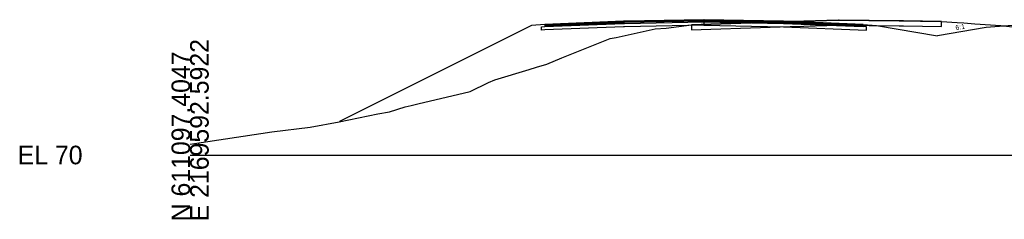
# Model space of a CAD drawing. Extents: x -26 to 1303, y -3010 to 12033.
# Drawn here: x 974.3 to 1122.8, y 6490.3 to 6520.4 of the extents above; entities that cross this region are included whole.
import ezdxf

# ---------------------------------------------------------------- set-up
doc = ezdxf.new("R2010")
doc.units = 0
for name, color, linetype in [('RD_GPK_XS_Cell', 7, 'Continuous'), ('RD_XS_Base', 7, 'Continuous'), ('RD_XS_ExGround', 7, 'Continuous'), ('RD_XS_ExPaveRet', 7, 'Continuous'), ('RD_XS_Greenside', 7, 'Continuous'), ('RD_XS_Pave', 7, 'Continuous'), ('RD_XS_PaveOvlay_CP', 7, 'Continuous'), ('RD_XS_TieSlope', 7, 'Continuous'), ('RD_XS_TX_Slope', 7, 'Continuous')]:
    doc.layers.add(name, color=color, linetype=linetype)

msp = doc.modelspace()

# ---------------------------------------------------------------- linework, layer by layer
at = {"layer": 'RD_GPK_XS_Cell'}
msp.add_line((1000, 6500), (1150, 6500), dxfattribs=at)
at = {"layer": 'RD_XS_Base'}
for p, q in [((1053.47, 6519.36), (1065.35, 6519.83)), ((1065.35, 6519.83), (1065.47, 6519.84)), ((1065.47, 6519.84), (1077.46, 6520.08)), ((1077.46, 6520.08), (1077.47, 6520.08)), ((1077.47, 6520.08), (1077.47, 6520.24)), ((1077.47, 6520.24), (1077.47, 6520.24)), ((1077.47, 6520.24), (1077.47, 6520.24)), ((1077.47, 6520.24), (1077.47, 6519.58)), ((1077.47, 6520.08), (1077.47, 6520.24)), ((1077.47, 6520.24), (1077.47, 6519.58)), ((1077.47, 6520.08), (1077.47, 6520.08)), ((1077.47, 6520.08), (1077.47, 6519.58)), ((1077.49, 6520.08), (1077.47, 6520.08)), ((1077.47, 6520.08), (1077.47, 6519.58)), ((1089.47, 6519.84), (1077.47, 6520.08)), ((1077.47, 6520.08), (1077.47, 6520.08)), ((1101.47, 6519.36), (1089.47, 6519.84)), ((1091.47, 6519.76), (1091.47, 6519.76)), ((1052.97, 6519.34), (1053.46, 6519.36)), ((1052.97, 6519.33), (1052.97, 6519.34)), ((1052.97, 6518.84), (1052.97, 6519.33)), ((1053.46, 6518.86), (1052.97, 6518.84)), ((1053.46, 6519.36), (1053.47, 6519.36)), ((1053.47, 6518.86), (1053.46, 6518.86)), ((1065.35, 6519.33), (1053.47, 6518.86)), ((1065.47, 6519.34), (1065.35, 6519.33)), ((1077.46, 6519.58), (1065.47, 6519.34)), ((1077.47, 6519.58), (1077.46, 6519.58)), ((1077.47, 6519.58), (1077.49, 6519.58)), ((1077.47, 6519.58), (1077.47, 6519.58)), ((1077.47, 6519.58), (1077.47, 6519.58)), ((1077.47, 6519.58), (1089.47, 6519.34)), ((1089.47, 6519.34), (1101.97, 6518.84)), ((1091.47, 6519.26), (1091.47, 6519.26)), ((1101.97, 6519.34), (1101.47, 6519.36)), ((1101.47, 6519.36), (1101.47, 6519.36)), ((1101.97, 6518.84), (1101.97, 6519.34)), ((1101.97, 6519.34), (1101.97, 6519.34)), ((1101.97, 6518.84), (1101.97, 6518.84)), ((1101.97, 6518.84), (1101.97, 6518.84))]:
    msp.add_line(p, q, dxfattribs=at)
at = {"layer": 'RD_XS_ExGround'}
msp.add_lwpolyline([(1000, 6501.64), (1012.31, 6503.47), (1018.1, 6504.19), (1022.48, 6505.02), (1028.31, 6506.21), (1030.05, 6506.49), (1032.43, 6507.28), (1033.34, 6507.48), (1034.34, 6507.73), (1042.21, 6509.55), (1044.98, 6510.92), (1045.94, 6511.35), (1051.14, 6512.9), (1052.23, 6513.25), (1053.8, 6513.7), (1056.05, 6514.64), (1063.34, 6517.57), (1064.25, 6517.73), (1070.09, 6519), (1071.78, 6519.12), (1075.61, 6519.63), (1090.46, 6520.11), (1097.77, 6520.34), (1106.9, 6520.22), (1113.29, 6520.13), (1115.64, 6519.97), (1116.64, 6519.9), (1118.29, 6519.78), (1122.24, 6519.5), (1130.02, 6518.62)], dxfattribs=at)
at = {"layer": 'RD_XS_ExPaveRet'}
for points in [[(1075.61, 6519.63), (1075.61, 6519.63), (1075.61, 6519.63), (1075.61, 6518.96), (1075.61, 6518.88), (1075.61, 6518.88), (1075.61, 6518.88), (1078.52, 6518.97), (1090.46, 6519.36), (1090.79, 6519.37), (1097.77, 6519.59), (1097.83, 6519.59), (1106.9, 6519.47), (1107.54, 6519.46), (1113.29, 6519.38), (1113.29, 6519.38), (1113.29, 6519.38), (1113.29, 6520.09), (1113.29, 6520.13), (1113.29, 6520.13), (1113.29, 6520.13), (1107.54, 6520.21), (1106.9, 6520.22), (1097.83, 6520.34), (1097.77, 6520.34), (1090.79, 6520.12), (1090.46, 6520.11), (1078.52, 6519.72), (1075.61, 6519.63)], [(1075.61, 6519.63), (1075.61, 6519.63), (1075.61, 6518.96), (1075.61, 6518.88), (1075.61, 6518.88), (1078.52, 6518.97), (1090.46, 6519.36), (1090.79, 6519.37), (1097.77, 6519.59), (1097.83, 6519.59), (1106.9, 6519.47), (1107.54, 6519.46), (1113.29, 6519.38), (1113.29, 6519.38), (1113.29, 6520.09), (1113.29, 6520.13), (1113.29, 6520.13), (1107.54, 6520.21), (1106.9, 6520.22), (1097.83, 6520.34), (1097.77, 6520.34), (1090.79, 6520.12), (1090.46, 6520.11), (1078.52, 6519.72), (1075.61, 6519.63)]]:
    msp.add_lwpolyline(points, dxfattribs=at)
at = {"layer": 'RD_XS_Greenside'}
for p, q in [((1051.47, 6519.52), (1022.54, 6505.06)), ((1103.47, 6519.52), (1112.69, 6517.98)), ((1120, 6519.2), (1112.69, 6517.98))]:
    msp.add_line(p, q, dxfattribs=at)
at = {"layer": 'RD_XS_Pave'}
for p, q in [((1065.35, 6520.15), (1053.47, 6519.68)), ((1065.35, 6519.99), (1053.47, 6519.52)), ((1053.47, 6519.52), (1065.35, 6519.99)), ((1053.47, 6519.36), (1065.35, 6519.83)), ((1053.47, 6519.68), (1053.47, 6519.67)), ((1053.47, 6519.67), (1053.47, 6519.52)), ((1065.47, 6520.16), (1065.35, 6520.15)), ((1065.47, 6520), (1065.35, 6519.99)), ((1065.35, 6519.99), (1065.47, 6520)), ((1065.35, 6519.83), (1065.47, 6519.84)), ((1077.46, 6520.4), (1065.47, 6520.16)), ((1077.46, 6520.24), (1065.47, 6520)), ((1065.47, 6520), (1077.46, 6520.24)), ((1065.47, 6519.84), (1077.46, 6520.08)), ((1077.47, 6520.4), (1077.46, 6520.4)), ((1077.47, 6520.24), (1077.46, 6520.24)), ((1077.46, 6520.24), (1077.47, 6520.24)), ((1077.46, 6520.08), (1077.47, 6520.08)), ((1077.49, 6520.4), (1077.47, 6520.4)), ((1089.47, 6520.16), (1077.47, 6520.4)), ((1077.47, 6520.08), (1077.47, 6520.24)), ((1077.47, 6520.24), (1077.47, 6520.24)), ((1077.47, 6520.24), (1077.49, 6520.24)), ((1077.49, 6520.24), (1077.47, 6520.24)), ((1077.47, 6520.24), (1077.47, 6520.24)), ((1077.47, 6520.24), (1077.47, 6520.08)), ((1077.47, 6520.08), (1077.47, 6520.24)), ((1077.47, 6520.24), (1089.47, 6520)), ((1089.47, 6520), (1077.47, 6520.24)), ((1077.47, 6520.24), (1077.47, 6520.08)), ((1077.47, 6520.08), (1077.49, 6520.08)), ((1077.47, 6520.08), (1077.47, 6520.08)), ((1077.47, 6520.08), (1077.47, 6520.08)), ((1077.47, 6520.08), (1089.47, 6519.84)), ((1101.47, 6519.68), (1089.47, 6520.16)), ((1089.47, 6520), (1101.47, 6519.52)), ((1101.47, 6519.52), (1089.47, 6520)), ((1089.47, 6519.84), (1101.47, 6519.36)), ((1091.47, 6520.08), (1091.47, 6520.08)), ((1091.47, 6519.92), (1091.47, 6519.92)), ((1091.47, 6519.92), (1091.47, 6519.92)), ((1091.47, 6519.76), (1091.47, 6519.76)), ((1101.47, 6519.52), (1101.47, 6519.68)), ((1101.47, 6519.68), (1101.47, 6519.68)), ((1053.47, 6519.52), (1053.47, 6519.52)), ((1053.47, 6519.52), (1053.47, 6519.36)), ((1101.47, 6519.52), (1101.47, 6519.52)), ((1101.47, 6519.52), (1101.47, 6519.52)), ((1101.47, 6519.36), (1101.47, 6519.52)), ((1101.47, 6519.52), (1101.47, 6519.52)), ((1101.47, 6519.36), (1101.47, 6519.36)), ((1101.47, 6519.36), (1101.47, 6519.36))]:
    msp.add_line(p, q, dxfattribs=at)
at = {"layer": 'RD_XS_PaveOvlay_CP'}
for p, q in [((1053.47, 6519.68), (1065.47, 6520.16)), ((1065.47, 6520.16), (1077.47, 6520.4)), ((1077.47, 6520.4), (1089.47, 6520.16)), ((1089.47, 6520.16), (1101.47, 6519.68))]:
    msp.add_line(p, q, dxfattribs=at)
at = {"layer": 'RD_XS_TieSlope'}
for p, q in [((1053.47, 6519.68), (1051.47, 6519.52)), ((1101.47, 6519.68), (1103.47, 6519.52)), ((1126, 6519.68), (1120, 6519.2))]:
    msp.add_line(p, q, dxfattribs=at)

# ---------------------------------------------------------------- texts
at = {"layer": 'RD_GPK_XS_Cell'}
for s, p in [('E 2169592.5922', (1002.8, 6490)), ('N 611097.4047', (1000, 6490))]:
    msp.add_text(s, height=2.8, rotation=90, dxfattribs=at).set_placement(p)
msp.add_text('EL 70', height=2.8, dxfattribs=at).set_placement((974, 6498.6))
at = {"layer": 'RD_XS_TX_Slope'}
msp.add_text('6:1', height=0.75, rotation=9.4642, dxfattribs=at).set_placement((1115.45, 6518.81))

doc.saveas('drawing.dxf')
